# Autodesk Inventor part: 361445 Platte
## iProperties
Company: Mayer & Müller AG Schaltgeräte
Created: 2006-10
Part Number: 361445 Platte
Material: 1.0330.03
Description: Segment
Document SubType Name: Modeling
Designer: Natti_01
Cost Center: 0,229 kg
Authority: 29224 mm^3
Density: 7.84 g/cm^3
HalbzeugNorm: DIN 1541
Zweck: 266493
Abmessung: St. Bl. 3x1000x2000
SaveDate: 2006-11-05
SaveTime: 20:39
TotalMass: 0,229 kg
TotalVolume: 29224 mm^3
Author: Natti_01
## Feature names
1. Extrusion3
2. Bohrung1 [Hole]
3. Runde Anordnung1 [Circular Pattern]
